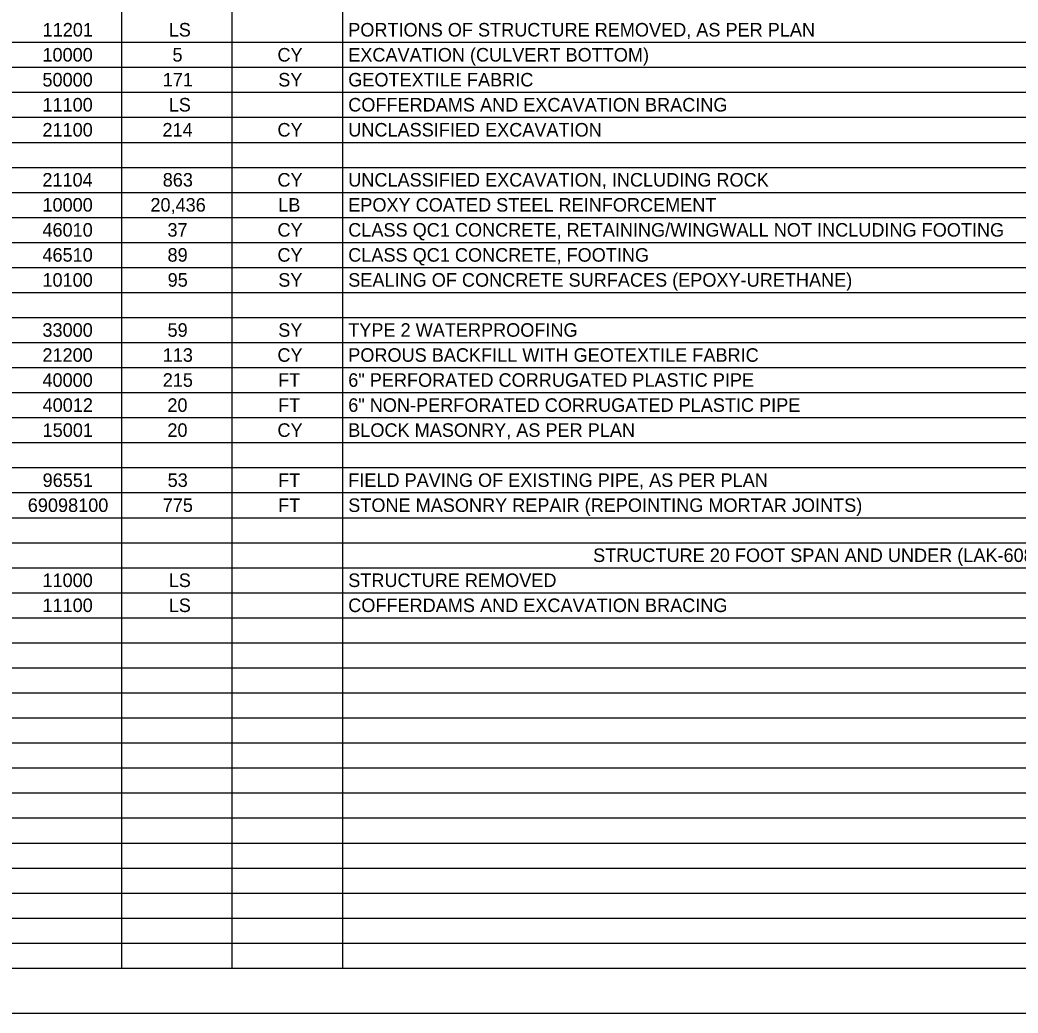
# Model space of a CAD drawing. Extents: x 0 to 34, y 0 to 22.
# Drawn here: x 16.9 to 28.07, y 0 to 11.11 of the extents above; entities that cross this region are included whole.
import ezdxf

# ---------------------------------------------------------------- set-up
doc = ezdxf.new("R2010")
doc.units = 0
for name, color, linetype in [('SH_Border', 7, 'Continuous'), ('SH_Cut_Line', 7, 'Continuous'), ('SH_Text', 7, 'Continuous')]:
    doc.layers.add(name, color=color, linetype=linetype)

msp = doc.modelspace()

# ---------------------------------------------------------------- linework, layer by layer
at = {"layer": 'SH_Border'}
msp.add_lwpolyline([(1.5, 21.5), (33.5, 21.5), (33.5, 0.5), (1.5, 0.5)], close=True, dxfattribs=at)
at = {"layer": 'SH_Cut_Line'}
msp.add_lwpolyline([(0, 0), (34, 0), (34, 22), (0, 22)], close=True, dxfattribs=at)
at = {"layer": 'SH_Text'}
for p, q in [((18.035, 21.5), (18.035, 0.502)), ((19.27, 21.5), (19.27, 0.502)), ((20.505, 21.5), (20.505, 0.502)), ((1.5, 10.861), (32, 10.861)), ((1.5, 10.581), (32, 10.581)), ((1.5, 10.301), (32, 10.301)), ((1.5, 10.021), (32, 10.021)), ((1.5, 9.741), (32, 9.741)), ((1.5, 9.461), (32, 9.461)), ((1.5, 9.181), (32, 9.181)), ((1.5, 8.901), (32, 8.901)), ((1.5, 8.621), (32, 8.621)), ((1.5, 8.342), (32, 8.342)), ((1.5, 8.062), (32, 8.062)), ((1.5, 7.782), (32, 7.782)), ((1.5, 7.502), (32, 7.502)), ((1.5, 7.222), (32, 7.222)), ((1.5, 6.942), (32, 6.942)), ((1.5, 6.662), (32, 6.662)), ((1.5, 6.382), (32, 6.382)), ((1.5, 6.102), (32, 6.102)), ((1.5, 5.822), (32, 5.822)), ((1.5, 5.542), (32, 5.542)), ((1.5, 5.262), (32, 5.262)), ((1.5, 4.982), (32, 4.982)), ((1.5, 4.702), (32, 4.702)), ((1.5, 4.422), (32, 4.422)), ((1.5, 4.142), (32, 4.142)), ((1.5, 3.862), (32, 3.862)), ((1.5, 3.582), (32, 3.582)), ((1.5, 3.302), (32, 3.302)), ((1.5, 3.022), (32, 3.022)), ((1.5, 2.742), (32, 2.742)), ((1.5, 2.462), (32, 2.462)), ((1.5, 2.182), (32, 2.182)), ((1.5, 1.902), (32, 1.902)), ((1.5, 1.622), (32, 1.622)), ((1.5, 1.342), (32, 1.342)), ((1.5, 1.062), (32, 1.062)), ((1.5, 0.782), (32, 0.782)), ((1.5, 0.502), (32, 0.502))]:
    msp.add_line(p, q, dxfattribs=at)

# ---------------------------------------------------------------- texts
for s, height, p in [('11201', 0.1515, (17.151, 10.925)), ('LS', 0.1515, (18.562, 10.925)), ('PORTIONS OF STRUCTURE REMOVED, AS PER PLAN', 0.15151, (20.571, 10.925)), ('10000', 0.1515, (17.149, 10.645)), ('5', 0.152, (18.604, 10.645)), ('CY', 0.1515, (19.779, 10.645)), ('EXCAVATION (CULVERT BOTTOM)', 0.15151, (20.571, 10.645)), ('50000', 0.1515, (17.149, 10.366)), ('171', 0.1515, (18.495, 10.366)), ('SY', 0.1515, (19.788, 10.366)), ('GEOTEXTILE FABRIC', 0.15151, (20.571, 10.366)), ('11100', 0.1515, (17.149, 10.086)), ('LS', 0.1515, (18.562, 10.086)), ('COFFERDAMS AND EXCAVATION BRACING', 0.15151, (20.571, 10.086)), ('21100', 0.1515, (17.149, 9.806)), ('214', 0.1515, (18.492, 9.806)), ('CY', 0.1515, (19.779, 9.806)), ('UNCLASSIFIED EXCAVATION', 0.15151, (20.571, 9.806)), ('21104', 0.1515, (17.148, 9.246)), ('863', 0.1515, (18.495, 9.246)), ('CY', 0.1515, (19.779, 9.246)), ('UNCLASSIFIED EXCAVATION, INCLUDING ROCK', 0.15151, (20.571, 9.246)), ('10000', 0.1515, (17.149, 8.966)), ('20,436', 0.1515, (18.357, 8.966)), ('LB', 0.1515, (19.788, 8.966)), ('EPOXY COATED STEEL REINFORCEMENT', 0.15151, (20.571, 8.966)), ('46010', 0.1515, (17.149, 8.686)), ('37', 0.1515, (18.548, 8.686)), ('CY', 0.1515, (19.779, 8.686)), ('CLASS QC1 CONCRETE, RETAINING/WINGWALL NOT INCLUDING FOOTING', 0.15151, (20.571, 8.686)), ('46510', 0.1515, (17.149, 8.406)), ('89', 0.1515, (18.549, 8.406)), ('CY', 0.1515, (19.779, 8.406)), ('CLASS QC1 CONCRETE, FOOTING', 0.15151, (20.571, 8.406)), ('10100', 0.1515, (17.149, 8.126)), ('95', 0.1515, (18.55, 8.126)), ('SY', 0.1515, (19.788, 8.126)), ('SEALING OF CONCRETE SURFACES (EPOXY-URETHANE)', 0.15151, (20.571, 8.126)), ('33000', 0.1515, (17.149, 7.566)), ('59', 0.1515, (18.549, 7.566)), ('SY', 0.1515, (19.788, 7.566)), ('TYPE 2 WATERPROOFING', 0.15151, (20.571, 7.566)), ('21200', 0.1515, (17.149, 7.286)), ('113', 0.1515, (18.495, 7.286)), ('CY', 0.1515, (19.779, 7.286)), ('POROUS BACKFILL WITH GEOTEXTILE FABRIC', 0.15151, (20.571, 7.286)), ('40000', 0.1515, (17.149, 7.006)), ('215', 0.1515, (18.495, 7.006)), ('FT', 0.1515, (19.786, 7.006)), ('6" PERFORATED CORRUGATED PLASTIC PIPE', 0.15151, (20.571, 7.006)), ('40012', 0.1515, (17.151, 6.726)), ('20', 0.1515, (18.547, 6.726)), ('FT', 0.1515, (19.786, 6.726)), ('6" NON-PERFORATED CORRUGATED PLASTIC PIPE', 0.15151, (20.571, 6.726)), ('15001', 0.1515, (17.151, 6.446)), ('20', 0.1515, (18.547, 6.446)), ('CY', 0.1515, (19.779, 6.446)), ('BLOCK MASONRY, AS PER PLAN', 0.15151, (20.571, 6.446)), ('96551', 0.1515, (17.151, 5.886)), ('53', 0.1515, (18.55, 5.886)), ('FT', 0.1515, (19.786, 5.886)), ('FIELD PAVING OF EXISTING PIPE, AS PER PLAN', 0.15151, (20.571, 5.886)), ('69098100', 0.1515, (16.985, 5.606)), ('775', 0.1515, (18.495, 5.606)), ('FT', 0.1515, (19.786, 5.606)), ('STONE MASONRY REPAIR (REPOINTING MORTAR JOINTS)', 0.15151, (20.571, 5.606)), ('STRUCTURE 20 FOOT SPAN AND UNDER (LAK-608-3.10)', 0.15151, (23.311, 5.046)), ('11000', 0.1515, (17.149, 4.766)), ('LS', 0.1515, (18.562, 4.766)), ('STRUCTURE REMOVED', 0.15151, (20.571, 4.766)), ('11100', 0.1515, (17.149, 4.486)), ('LS', 0.1515, (18.562, 4.486)), ('COFFERDAMS AND EXCAVATION BRACING', 0.15151, (20.571, 4.486))]:
    msp.add_text(s, height=height, dxfattribs=at).set_placement(p)

doc.saveas('drawing.dxf')
